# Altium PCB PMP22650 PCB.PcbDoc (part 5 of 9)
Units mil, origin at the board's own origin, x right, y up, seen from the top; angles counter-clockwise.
Board outline 11311 x 5233 mil, 8 copper layers (Layer 1, Layer 2, Layer 3, Layer 4, Layer 5, Layer 6, Layer 7, Layer 8), stack 88.6 mil thick; 633 components, 410 nets, 2503 pads, 1993 vias.
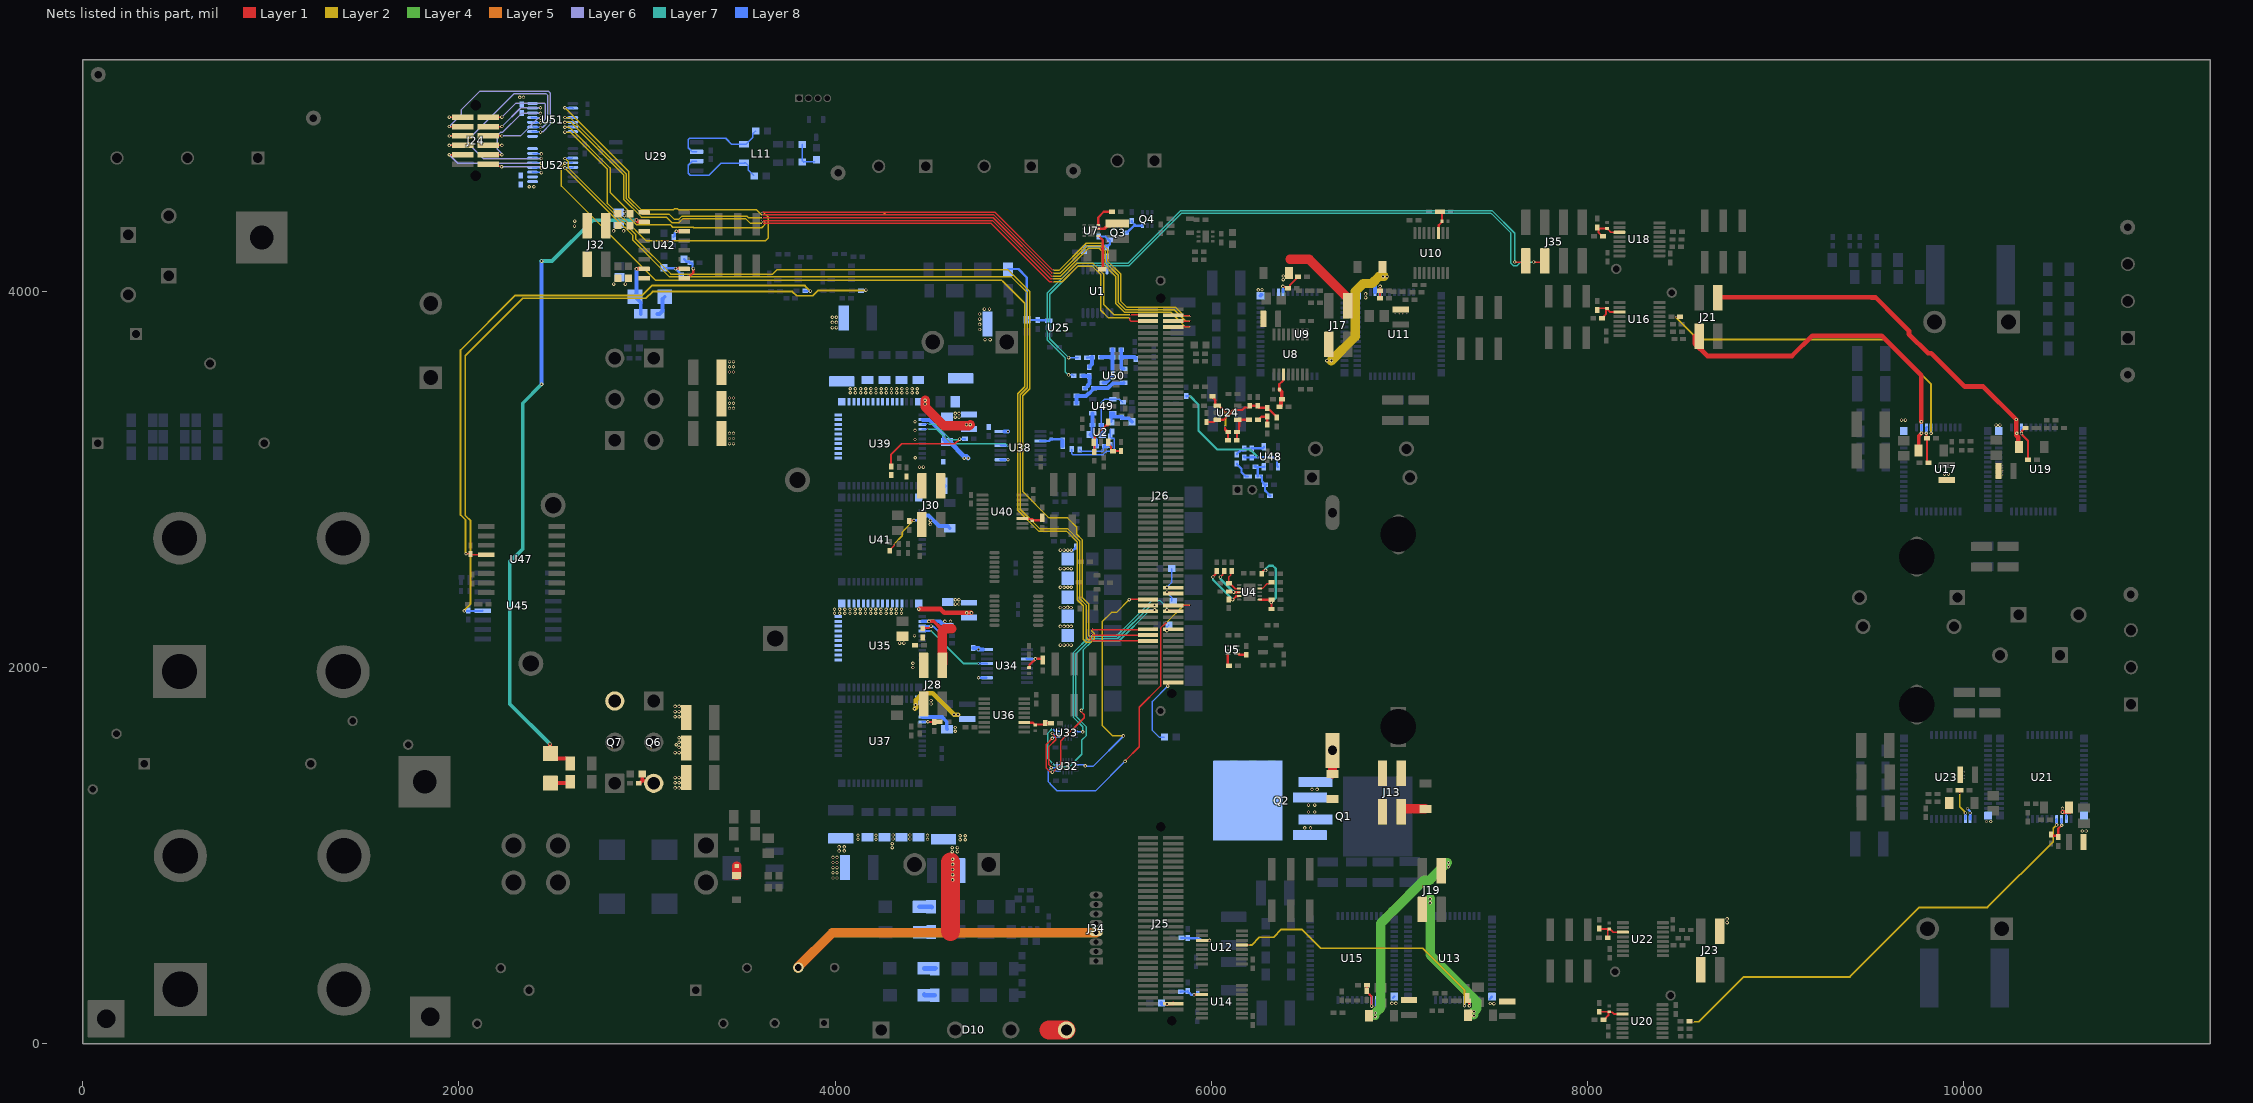
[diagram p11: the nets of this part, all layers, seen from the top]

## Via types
v1: diameter 18, hole 10, Layer 1 to Layer 8, 1759 vias
v2: diameter 8, hole 4, Layer 1 to Layer 2, 160 vias
v3: diameter 18, hole 10, Layer 1 to Layer 8, tented both sides, 34 vias
v4: diameter 8, hole 4, Layer 7 to Layer 8, 28 vias
v5: diameter 19.68, hole 7.87, Layer 1 to Layer 8, 8 vias
v6: diameter 118.11, hole 86.61, Layer 1 to Layer 8, 4 vias

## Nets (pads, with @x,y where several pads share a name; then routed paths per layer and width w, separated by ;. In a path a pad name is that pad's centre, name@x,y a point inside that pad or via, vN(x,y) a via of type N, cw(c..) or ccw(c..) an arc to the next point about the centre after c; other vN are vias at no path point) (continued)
FAULT_L_B: U12.5 U13.46 | length 1469
  Layer 1 w10: U12.5@6162.57,526.05 v2(6201,526)
  Layer 2 w10: v2(6201,526) 6213.5,526 6255.09,567.59 6330.59,567.59 6372,609 6481.43,609 6581.43,509 7123.84,509 7346.44,286.4 7346.44,203.44 v1(7346,203)
  Layer 8 w10: v1(7346,203) 7346.02,232.02 U13.46@7347,233 ; U13.46@7346.03,236.83 U13.46@7348.27,234.6
FAULT_L_C: R211.2 U17.46 | length 1811.7
  Layer 1 w10: v2(8472,3866) R211.2@8482.62,3866
  Layer 2 w10: v2(8472,3866) 8472,3861.41 8588.3,3745.1 9590.06,3745.1 9827,3508.16 v1(9827,3247)
  Layer 8 w10: U17.46@9826,3279 U17.46@9826.94,3278.06 ; U17.46@9826.91,3278.02 U17.46@9826.94,3278.06 ; v1(9827,3247) v1(9827,3247) U17.46@9826.95,3278.05 ; U17.46@9828.04,3279.16 U17.46@9826.94,3278.06
FAULT_L_D: R216.2 U21.46 | length 2463.8
  Layer 1 w10: R216.2@8539,118 v2(8562,118)
  Layer 2 w10: v2(8562,118) 8592,118 8831,357 9394.73,357 9763.73,726 10126,726 10476.23,1076.23 10476.23,1147.23 v1(10494,1165)
  Layer 8 w10: U21.46@10491.18,1192.98 U21.46@10494.05,1195.86 ; U21.46@10493,1194 10494.02,1192.98 v1(10494,1165)
FAULT_L_PFC_1: U34.5 U35.46 | length 417.2
  Layer 7 w10: v4(4510,2195.65) 4683.55,2022.1 v4(4761.97,2022.1)
  Layer 8 w10: U35.46@4463.12,2195.65 v4(4510,2195.65) ; v4(4761.97,2022.1) U34.5@4806.97,2022.1 4807.77,2022.1 U34.5@4808.27,2022.6
FAULT_L_PFC_2: U38.5 U39.46 | length 532.8
  Layer 7 w8: v4(4492.12,3268.14) 4540.59,3268.14 4618.3,3190.43 4907.57,3190.43 v4@4918,3180
  Layer 8 w8: U39.46@4463.27,3268.6 4463.72,3268.14 v4(4492.12,3268.14) ; U38.5@4878.27,3182.6 4879.77,3181.1 v4(4918.97,3181.1)
FET_TEMP_MUX_OUT1: J26.91 U32.6 | length 1299.9
  Layer 1 w8: v1@5569.27,2363.3 5569.37,2363.19 5663.3,2363.19 J26.91@5663.41,2363.09
  Layer 2 w8: v1(5532,1638) 5530.5,1639.5 5473.41,1639.5 5465.5,1647.41 5418.77,1694.14 5418.77,2244.26 5468.9,2294.39 5495.06,2294.39 v1(5563.27,2362.6)
  Layer 8 w8: U32.6@5282.28,1484.35 5323.52,1484.35 v1(5329.27,1478.6) ; v1@5323.27,1477.6 5329.27,1477.6 5373.31,1477.6 5532,1636.29 v1(5532,1638)
FET_TEMP_MUX_OUT2: J26.96 U33.6 | length 1176.9
  Layer 1 w8: v1(5763.27,2307.6) 5765.43,2307.6 5767.09,2305.94 5814.93,2305.94 J26.96@5818.27,2302.6
  Layer 7 w8: v1(5316,1659) 5316,1686.71 5265,1737.71 5265,2078.74 5353.86,2167.6 5494.43,2167.6 5575.93,2249.1 5682.43,2355.6 5729.4,2355.6 5763.27,2321.73 v1(5763.27,2307.6)
  Layer 8 w8: U33.6@5279.42,1662.07 5281.73,1659.76 5315.24,1659.76 v1(5316,1659)
FET_TEMP_MUX_SEL0: J26.93 U32.15 U33.15 | length 1626.4
  Layer 1 w8: J26.93@5633.27,2327.6 J26.93@5698.27,2327.6
  Layer 7 w8: v4(5154.79,1675.68) 5153.66,1675.68 5131.02,1653.04 5131.02,1516.36 v4(5154.79,1492.6) 5173.39,1474 5245.14,1474 5311.27,1540.13 5311.27,1616.1 5335.84,1640.66 5335.84,1685.97 5278.5,1743.3 5278.5,2073.15 5359.45,2154.1 5500.02,2154.1 5677.27,2331.34 5697.01,2331.34 v1(5698.27,2332.6)
  Layer 8 w8: v4(5154.79,1492.6) 5155.73,1492.6 5163.98,1484.35 U32.15@5187.79,1484.35 ; v4(5154.79,1675.68) 5155.98,1675.68 5169.53,1662.13 U33.15@5184.93,1662.07 U33.15@5184.93,1662.07
FET_TEMP_MUX_SEL1: J26.94 U32.14 U33.14 | length 1930.1
  Layer 1 w8: v1@5152.62,1468.6 5136.29,1484.94 5136.29,1581.12 5172.5,1617.34 5172.5,1632.93 v1(5154.79,1650.64) ; v1(5541.27,1502.6) 5541.27,1505.16 5616.5,1580.4 5616.5,1789.68 5730,1903.18 5730,2210.91 5747.59,2228.5 5749.59,2228.5 5760,2238.91 v2(5760,2244) ; J26.94@5783.49,2331.59 J26.94@5797.27,2331.59 ; J26.94@5818.27,2332.6 v2(5888.27,2332.6)
  Layer 2 w8: v2(5760,2244) 5764.67,2244 5853.27,2332.6 v2(5888.27,2332.6)
  Layer 8 w8: v1@5161.27,1646.32 U33.14@5184.93,1646.32 ; U32.14@5187.79,1468.6 5149.6,1468.6 5132,1451 5132,1396.12 5144.74,1383.37 5144.74,1380.42 5177.66,1347.5 5386.17,1347.5 v1(5541.27,1502.6)
  other v1: 5149,1469
FET_TEMP_MUX_SEL2: J26.95 U32.13 U33.13 | length 1519.1
  Layer 1 w8: v1(5154,1625) 5122.79,1593.79 5122.79,1466.21 5142.55,1446.45 5155.86,1446.45 5157.33,1444.98 5173.29,1460.94 5173.29,1462.35 5200,1489.07 5200,1544.7 5199.77,1544.94 5199.77,1610.84 5323.87,1734.94 5323.87,1750.26 5309.17,1764.96 v1(5309.17,1773.25) ; J26.95@5663.41,2300.09 5669.25,2305.94 5694.44,2305.94 5696.1,2307.6 v1(5698.27,2307.6)
  Layer 7 w8: v1(5309.17,1773.25) 5318.27,1782.34 5318.27,2093.83 5365.04,2140.6 5507.18,2140.6 5674.18,2307.6 v1(5698.27,2307.6)
  Layer 8 w8: v1(5154,1625) 5159.57,1630.57 U33.13@5184.93,1630.57 ; v1(5154.79,1444.98) 5156.95,1444.98 5165.05,1453.08 5179.82,1453.08 5180.04,1452.85 U32.13@5187.79,1452.85
FSI_TX_CLK: J26.105 U52.3 | length 5218.2
  Layer 1 w8: v2(5348.27,2162.6) 5368.27,2142.6 J26.105@5643.27,2142.6
  Layer 2 w8: v1(2563.27,4707.6) 2564.43,4707.6 2581.77,4690.26 2581.77,4656.98 2866.75,4372 2871.79,4372 2938.5,4305.29 2938.5,4281.19 3126.69,4093 3667.79,4093 3690.89,4116.1 4125.93,4116.1 4127.03,4115 4920,4115 5034.5,4000.5 5034.5,3483.22 4997.5,3446.22 4997.5,2936.5 5137.5,2796.5 5235.53,2796.5 5284.5,2747.53 5284.5,2709.78 5314.36,2679.91 5314.36,2372.55 5348.27,2338.64 v2(5348.27,2162.6)
  Layer 8 w8: v1(2563.27,4707.6) 2564.52,4708.85 2599.52,4708.85 U52.3@2603.27,4712.6
FSI_TX_D0: J26.101 U52.4 | length 5332.1
  Layer 1 w8: v2(5363.27,2207.6) 5368.27,2202.6 5628.27,2202.6 J26.101@5633.27,2207.6
  Layer 2 w8: v1(2563.27,4682.6) 2562.1,4682.6 2544.77,4665.26 2544.77,4561.24 3046.51,4059.5 4886.31,4059.5 4891,4054.81 5007.5,3938.31 5007.5,3494.41 4970.5,3457.41 4970.5,2837.41 5081.41,2726.5 5229.59,2726.5 5287.36,2668.73 5287.36,2361.36 5319.06,2329.67 5319.06,2151.94 5335,2136 5336.68,2136 5337.08,2135.6 5360.6,2135.6 5375,2150 5375,2151.15 5376.77,2152.91 5376.77,2183.19 5363.27,2196.69 v2(5363.27,2207.6)
  Layer 8 w8: v1(2563.27,4682.6) 2564.52,4683.85 2599.52,4683.85 U52.4@2603.27,4687.6
FSI_TX_D1: J26.103 U52.5 | length 5215.1
  Layer 1 w8: v2(5363.27,2177.6) 5368.27,2172.6 5633.27,2172.6 J26.103@5638.27,2177.6
  Layer 2 w8: v1(2563.27,4657.6) 2563.27,4656.39 2878.05,4341.6 2883.1,4341.6 2893.94,4330.77 2893.94,4330.06 2925,4299 2925,4272.69 3119.69,4078 4937.91,4078 5021,3994.91 5021,3488.82 4984,3451.82 4984,2843 5087,2740 5235.18,2740 5300.86,2674.32 5300.86,2366.96 5334.27,2333.55 5334.27,2157.51 5342.68,2149.1 5353.86,2149.1 5363.27,2158.51 v2(5363.27,2177.6)
  Layer 8 w8: v1(2563.27,4657.6) 2564.52,4658.85 2604.52,4658.85 U52.5@2608.27,4662.6
IAC_PH1_SENSOR: C211.1 R146.1 U47.12 | length 3250
  Layer 1 w10: v1@2036,2605 v1(2037,2606) 2059.24,2606 C211.1@2061.27,2603.98 ; C211.1@2059,2604 2062,2601 U47.12@2144.99,2601
  Layer 2 w10: v1@2035,2613.66 2035,2785.72 2008,2812.72 2008,3689.33 2298.67,3980 2974,3980 3025.5,4031.5 3839.37,4031.5 v1(3868.27,4002.6)
  Layer 8 w10: R146.1@3833.27,4002.6 3833.75,4003.08 3867.78,4003.08 v1(3868.27,4002.6)
IAC_PH2_SENSOR: C204.1 R131.1 U45.12 | length 3806.6
  Layer 2 w10: v1@2025,2303 2026.5,2303 2029.8,2306.29 2029.8,2307.8 2062,2340 2062,2780.64 2033,2809.64 2033,3659.33 2338.17,3964.5 2993.87,3964.5 3029.72,4000.35 3772.25,4000.35 3794.6,3978 3880,3978 3907.64,4005.64 4157.07,4005.64 4157.88,4006.45 v1@4163.42,4006.45
  Layer 8 w10: v1(2028.27,2302.6) 2125.26,2302.6 U45.12@2126.26,2303.6 ; R131.1@4133.27,4007.6 4134.42,4006.45 4162.12,4006.45 v1(4163.27,4007.6)
IN_H_A: C57.2 R34.2 U11.45 | length 103
  Layer 1 w10: v1@6897,4029 6897.27,4028.73 v1(6897.27,4028) 6897.27,4004.11 C57.2@6897.38,4004 6897.38,3966.62 R34.2@6901,3963
  Layer 8 w10: U11.45@6897,3993 6896.72,3993.28 6896.72,4027.45 v1(6897.27,4028)
IN_H_B: C79.2 R44.2 U15.45 | length 155.9
  Layer 1 w12: R44.2@6826.62,313 6826.81,312.81 6826.81,281.19 C79.2@6827,281 ; C79.2@6827,280.62 6827,276.68 6841.85,261.83 6842.37,261.83 6852,252.2 v1(6852,201)
  Layer 8 w12: U15.45@6851,234 6851.81,233.19 6851.81,201.19 v1(6852,201)
IN_H_C: C101.2 R54.2 U19.45 | length 239.7
  Layer 1 w12: v1(10307,3246) 10307,3244.38 10311.5,3239.88 10311.5,3237.51 10342.38,3206.63 10342.38,3106.38 R54.2@10342,3106 ; v1@10308,3247 10308.15,3247.15 10308.15,3258.71 10324.44,3275 C101.2@10328.38,3275 10330.07,3275 C101.2@10335.88,3269.19 ; C101.2@10325.44,3274 C101.2@10330,3274
  Layer 8 w12: U19.45@10306.31,3278.02 10306.66,3277.68 10306.66,3248.34 v1@10308,3247
IN_H_D: C123.2 R64.2 U23.45 | length 165.5
  Layer 1 w10: R64.2@9978,1347 9979,1346 v2(9979,1331)
  Layer 2 w10: v2(9979,1331) 9979,1260.58 10003.5,1236.08 10003.5,1235.66 10008,1231.16 v3@10008,1226
  Layer 8 w12: U23.45@10009,1196 10008.9,1196.1 10008.9,1227.9 v3(10009,1228)
IN_H_PFC_1: C165.2 R105.2 U37.45 | length 95.3
  Layer 1 w10: v1@4492.9,1712.6 v1(4493.12,1712.82) 4493.34,1712.6 4525.35,1712.6 4526.47,1711.47 C165.2@4527.09,1710.85 ; C165.2@4525,1710 4527,1712 R105.2@4554.38,1712
  Layer 8 w10: U37.45@4463.27,1712.6 4463.49,1712.82 v1(4493.12,1712.82)
IN_H_PFC_2: C187.2 R115.2 U41.45 | length 296.5
  Layer 1 w8: R115.2@4293,2622 4293,2628.31 4313,2648.31 v2(4313,2658) ; C187.2@4387.37,2771.37 C187.2@4390,2774 ; C187.2@4389,2782.62 4390.38,2784 4418,2784 v1@4421,2781 ; v1(4419,2784) v1@4420,2785
  Layer 2 w8: v2(4313,2658) 4356.5,2701.5 4356.5,2722.26 4417,2782.76 v1@4417,2783
  Layer 8 w12: v1@4418,2784 v1(4419,2784) 4462.96,2784 U41.45@4463.12,2784.16
IN_L_A: C42.2 R29.2 U9.45 | length 153.4
  Layer 1 w10: v1@6379,4029 6382.16,4029 6385.76,4025.41 6399.83,4025.41 C42.2@6406.65,4018.6 ; C42.2@6408,4020 6411.98,4020 6417.39,4025.41 6417.39,4034.02 6450.63,4067.25 6450.63,4071.19 6457.44,4078 R29.2@6461.38,4078
  Layer 8 w10: U9.45@6380,3996 6380.76,3996.76 6380.76,4027.24 v1(6380,4028) ; U9.45@6381.52,3996.71 U9.45@6384.39,3999.59
IN_L_B: C64.2 R39.2 U13.45 | length 96.9
  Layer 1 w12: R39.2@7361,258.38 7362.31,257.07 7362.31,231.69 C64.2@7365,229 ; C64.2@7363,233 7370.85,225.15 7370.85,204.15 v1(7372,203)
  Layer 8 w12: v1(7372,203) 7371.81,203.19 7371.81,234.81 U13.45@7372,235
IN_L_C: C86.2 R49.2 U17.45 | length 198.5
  Layer 1 w12: v1(9801,3247) 9802.15,3245.85 9802.15,3224.85 C86.2@9805,3222 ; C86.2@9804.38,3221 9804.38,3094.81 9812.19,3087 R49.2@9814,3087
  Layer 8 w12: v1(9801,3247) 9801.16,3247.16 9801.16,3277.16 U17.45@9803,3279
IN_L_D: C108.2 R59.2 U21.45 | length 139.7
  Layer 1 w12: R59.2@10464,1112.62 10464,1112.43 10469.81,1106.62 10498.38,1106.62 C108.2@10499.13,1105.87 ; C108.2@10503,1100.62 10503,1145 v1(10521,1163)
  Layer 8 w12: v1@10519.64,1164 U21.45@10519.64,1195.86
IN_L_PFC_1: C150.2 R100.2 U35.45 | length 181.6
  Layer 1 w10: C150.2@4466.27,2209.22 4469.05,2212 4499.13,2212 4508.37,2221.24 v1(4510,2221.24)
  Layer 8 w10: U35.45@4463.12,2221.24 v1(4510,2221.24) 4511.14,2220.1 4520.31,2220.1 4570.71,2169.7 R100.2@4574.65,2169.7
IN_L_PFC_2: C172.2 R110.2 U39.45 | length 726.4
  Layer 1 w10: C172.2@4297.27,3076.27 4297.27,3135.53 4352.74,3191 4637,3191 v1(4662,3216)
  Layer 7 w8: v4(4492.12,3293.73) 4534.09,3293.73 4616.09,3211.73 v1@4666.27,3211.73
  Layer 8 w8: U39.45@4463.12,3293.73 4463.25,3293.6 v4@4493.27,3293.6
  Layer 8 w10: v1(4662,3216) 4662.61,3216.61 4688.26,3216.61 R110.2@4690.27,3214.6 ; R110.2@4689.65,3216.62 R110.2@4690.65,3215.62
INJ: C235.1 J34.4 | length 1665.8
  Layer 5 w50: C235.1@3800,406 3985.44,591.44 J34.4@5387.63,591.44
  Layer 2 w50: C235.1@3804.26,406.24 C235.1@3805.24,407.22
IPRI_SENSE: C146.1 C148.2 C150.1 C151.2 C152.2 C153.2 C154.2 C155.1 C156.1 C157.2 C158.2 C159.1 C160.1 C168.1 C170.2 C172.1 C173.2 C174.2 C175.2 C176.2 C177.1 C178.1 C179.2 C180.2 C181.1 C182.1 C190.1 C191.1 C192.1 C196.2 C226.1 C227.1 C228.1 C229.1 C230.1 C231.1 D10.4 J28.4 J30.4 J32.4 L12.1 L14.1 Q6.3 Q7.3 R82.1 R97.1 R107.1 R118.1 R159.1 R164.1 R166.1 R171.1 R172.1 U34.2 U34.8 U35.17 U35.18 U35.19 U35.20 U35.21 U35.22 U35.23 U35.24 U35.25 U35.26 U35.27 U35.28 U35.29 U35.30 U35.31 U35.32 U35.33 U35.34 U35.35 U35.36 U35.37 U35.38 U35.39 U38.2 U38.8 U39.17 U39.18 U39.19 U39.20 U39.21 U39.22 U39.23 U39.24 U39.25 U39.26 U39.27 U39.28 U39.29 U39.30 U39.31 U39.32 U39.33 U39.34 U39.35 U39.36 U39.37 U39.38 U39.39 U42.9 | length 775.6
  Layer 1 w20: C196.2@2955.89,1385.6 2959.83,1385.6 2973.76,1399.54 ; R118.1@2973.76,1435.6 2973.76,1400.1 2974.29,1399.58 3021.33,1399.58 Q6.3@3035.21,1385.7
  Layer 1 w100: 4613.27,598.6 4613.27,872.6 4613.27,967.6 ; 5136.87,75 D10.4@5227,75
  Layer 5 w12: 4262.77,4418.1 4263.27,4417.6
  Layer 8 w12: v1(4761.97,1947.1) 4802.77,1947.1 U34.2@4803.27,1947.6 ; U38.2@4878.27,3107.6 4879.77,3106.1 v1(4918.97,3106.1) ; v1@5253.27,2624.6 5264.83,2624.6 5280.27,2640.04 R82.1@5280.27,2643.98
  Layer 8 w20: C148.2@4735.27,2104.75 v1@4761.97,2104.75 ; v1(4761.97,2097.1) 4762.68,2097.8 U34.8@4785.47,2097.8 ; U38.8@4900.46,3256.1 v1(4918.97,3256.1)
  other v1: 4624.54,872.6 3988.27,882.6 4009.54,882.6 4624.54,900.01 3988.27,910.01 4009.54,910.01 4624.54,927.41 3988.27,937.41 4009.54,937.41 4624.54,954.82 3988.27,964.82 4009.54,964.82 4624.54,982.23 3988.27,992.23 4009.54,992.23 4622.17,1022.72 4649.58,1022.72 4020.94,1026.72 4048.35,1026.72 4303.39,1043.72 4622.17,1044 4649.58,1044 4020.94,1048 4048.35,1048 4303.39,1065 4664.03,1085.72 4691.43,1085.72 4490.84,1087.72 4121.54,1088.72 4216.76,1088.72 4307.98,1089.72 4397.21,1089.72 4664.03,1107 4691.43,1107 4490.84,1109 4121.54,1110 4216.76,1110 4307.98,1111 4397.21,1111 3149.27,1361.59 3170.54,1361.59 3149.27,1389 3170.54,1389 3149.27,1416.41 3170.54,1416.41 3149.27,1549.26 3170.54,1549.26 3170.54,1576.66 3155,1591 3170.54,1604.07 3170,1628 3149.27,1739.78 3170.54,1739.78 3149.27,1767.19 3170.54,1767.19 3149.27,1794.6 3170.54,1794.6 4413.27,2001.49 4413.27,2024.28 5197.09,2120.85 5217.09,2120.85 5235.64,2121.16 5254.18,2120.85 4343,2131.24 4365.27,2131.24 4422,2171 5197.09,2220.21 5217.09,2220.21 5254.18,2220.21 5235.64,2220.52 3996.5,2289.69 4023.91,2289.69 4051.32,2289.69 4078.73,2289.69 4106.14,2289.69 4133.54,2289.69 4160.95,2289.69 4188.36,2289.69 4215.77,2289.69 4243.18,2289.69 4270.59,2289.69 4297.99,2289.69 4325.4,2289.69 4352.81,2289.69 3996.5,2310.97 4023.91,2310.97 4051.32,2310.97 4078.73,2310.97 4106.14,2310.97 4133.54,2310.97 4160.95,2310.97 4188.36,2310.97 4215.77,2310.97 4243.18,2310.97 4270.59,2310.97 4297.99,2310.97 4325.4,2310.97 4352.81,2310.97 5197.09,2320.56 5217.09,2320.56 5235.64,2320.87 5254.18,2320.56 4639.27,2338.63 4658,2339 4639.27,2361.43 4658,2362 5197.09,2428.04 5217.09,2428.04 5236.82,2428.35 5255.36,2428.04 5197.09,2527.39 5217.09,2527.39 5255.36,2527.39 5236.82,2527.7 5197.09,2625.3 5217.09,2625.3 5255.36,2625.3 5236.82,2625.61 4448.09,3067.17 4468.97,3067.17 4426,3117 3438.27,3191.59 3459.54,3191.59 4424.17,3214 3438.27,3219 3459.54,3219 3438.27,3246.41 3459.54,3246.41 4424.17,3262 4424.17,3308.36 4638.27,3332.6 4658.27,3332.6 4638.27,3352.6 4658.27,3352.6 3438.27,3379.26 3459.54,3379.26 3438.27,3406.66 3459.54,3406.66 3438.27,3434.07 3459.54,3434.07 4080.22,3462.52 4107.62,3462.52 4135.03,3462.52 4162.44,3462.52 4189.85,3462.52 4217.26,3462.52 4244.66,3462.52 4272.07,3462.52 4299.48,3462.52 4326.89,3462.52 4354.3,3462.52 4381.71,3462.52 4409.11,3462.52 4436.52,3462.52 4080.22,3483.8 4107.62,3483.8 4135.03,3483.8 4162.44,3483.8 4189.85,3483.8 4217.26,3483.8 4244.66,3483.8 4272.07,3483.8 4299.48,3483.8 4326.89,3483.8 4354.3,3483.8 4381.71,3483.8 4409.11,3483.8 4436.52,3483.8 3438.27,3572.78 3459.54,3572.78 3438.27,3600.19 3459.54,3600.19 3438.27,3627.6 3459.54,3627.6 4796.4,3744.77 4823.8,3744.77 4768.04,3798.6 3984.97,3808.78 4006.24,3808.78 4768.04,3826.01 3984.97,3836.19 4006.24,3836.19 4768.04,3853.42 3984.97,3863.6 4006.24,3863.6 4768.04,3880.83 4793.17,3906.77 4820.58,3906.77 2614.27,4348.08 2615.19,4374.6 2880,4404 2880,4425
ISNS_OUTN: J35.5 R199.1 | length 3441.9
  Layer 1 w8: v1(7713.02,4157.18) 7753.02,4157.18 7757.85,4157.18 J35.5@7758.27,4157.6
  Layer 7 w8: v1(5240.94,3649) 5141,3748.94 5141,3986.49 5293.01,4138.5 5563.59,4138.5 5842.59,4417.5 7484.5,4417.5 7486.86,4415.14 7488.96,4415.14 7593,4311.1 7593,4151 7605.32,4138.68 7626.68,4138.68 7645.18,4157.18 7710.18,4157.18 v1@7712,4159
  Layer 8 w8: v1(5240.94,3649) R199.1@5291.29,3649
ISNS_OUTP: J35.7 R195.1 | length 3423.7
  Layer 1 w8: v1(7613.02,4157.18) 7653.02,4157.18 7657.85,4157.18 J35.7@7658.27,4157.6
  Layer 2 w8: v1@5239,3557 v1@5240,3556
  Layer 7 w8: v1@5236,3560 5222.44,3573.56 5222.44,3648.41 5127.5,3743.34 5127.5,3992.5 5287,4152 5558,4152 5837,4431 7492.19,4431 7613.02,4310.17 v1(7613.02,4157.18)
  Layer 8 w8: v1(5241,3557) 5263.64,3557 R195.1@5268.32,3552.31
ISO_3.3V: C252.2 C254.2 J24.8 U51.1 U52.10 U52.16 | length 72.5
  Layer 1 w8: J24.8@2155.79,4777.6 v1(2228.27,4777.6)
ISO_12V_H_A: C59.1 J17.3 U11.44 | length 723.7
  Layer 2 w25: 6893,4079.6 v1(6913,4079.6)
  Layer 2 w50: v1(6638,3633) 6765,3760 6765,4000.47 6807.71,4043.18 6854.18,4043.18 6893,4082 v1@6918,4082
  Layer 8 w20: U11.44@6870.58,3996.71 6870.58,4050.58 6901,4081
  other v1: 6614,3633 6934,4079.6
ISO_12V_H_B: C81.1 J19.3 U15.44 | length 1061.3
  Layer 1 w25: J19.3@7211.36,949.36 J19.3@7222,960
  Layer 4 w50: v1@6870,153 6870,163.33 v1(6871.27,164.6) 6871.46,164.6 6901.5,194.64 6901.5,642.5 6967,708 ; 6961.5,702.12 7130.55,871.17 7160.89,871.17 v1@7253.89,964.17
  Layer 8 w12: v1(6871.27,164.6) v1@6871.27,166.22 ; 6877,185 6877.21,185.21 U15.44@6877.21,233.3
  other v1: 6870.43,145.48 7260.89,942 7260.89,963.17
ISO_12V_H_C: C103.1 J21.3 U19.44 | length 2083.8
  Layer 1 w25: J21.3@8693,3972 8694.43,3970.56 9506.6,3970.56 9508.13,3969.04 9530.96,3969.04 9649.47,3850.53 9708.72,3791.28 9708.72,3774.28 9810.23,3672.77 9827.23,3672.77 9886.49,3613.51 10005,3495 10104,3495 v1(10279,3320) v1@10279,3247 ; 10279,3235.82 10289.85,3224.96 10289.85,3177.22 C103.1@10294.07,3173
  Layer 8 w12: v1(10279,3320) 10279.86,3319.14 10279.86,3277.14 U19.44@10281,3276 ; U19.44@10280.72,3278.02 10281.36,3277.39 v1@10281.36,3247.36
  other v1: 10282,3247
ISO_12V_H_D: C125.1 J23.3 U23.44 | length 64.2
  Layer 8 w12: v3(10020,1252) 10020,1250.38 10032.85,1237.52 10032.85,1228.15 v3@10034,1227 ; v3(10034,1228) 10034.19,1227.81 10034.19,1195.81 U23.44@10035,1195
  other v1: 8742.27,644.83 8742.27,664.85
ISO_12V_H_PFC_1: C167.1 J28.3 U37.44 | length 181
  Layer 8 w20: U37.44@4463.12,1738.41 4567.33,1738.41 4592.92,1712.82 4592.92,1675.52 C167.1@4595.27,1673.17
  other v1: 4638.27,1662.6 4638.27,1682.6 4510,1807.6 4510,1826.23
ISO_12V_H_PFC_2: C189.1 J30.3 U41.44 | length 174.3
  Layer 8 w20: U41.44@4463.12,2809.75 4496.12,2809.75 4552.54,2753.32 4597.61,2753.32 C189.1@4609.27,2741.67
  other v1: 4506.27,2762.6 4506.27,2782.6
ISO_12V_H_RECT: C199.2 C200.2 C201.2 J32.3 U42.16
  other v1: 2822.5,4040.1 2884.5,4040.1
ISO_12V_L_A: C44.1 J17.2 U9.44 | length 434.1
  Layer 1 w50: 6418,4171 6520.78,4171 6725.01,3966.78 J17.2@6725.01,3924.26
  other v1: 6382,4064 6382,4083
ISO_12V_L_B: C66.1 J19.2 U13.44 | length 884.1
  Layer 1 w12: C66.1@7364,170 7366,172 v1(7396,172) ; C66.1@7366,151 v1(7396,151)
  Layer 1 w25: J19.2@7122,715.31 J19.2@7134.5,702.81
  Layer 4 w50: v1(7162.89,771.17) 7162.89,474.25 7411.5,225.64 7411.5,186.64 7396,171.14 v1@7396,156
  Layer 8 w12: v1@7394,171 7396.61,173.61 7396.61,232.69 U13.44@7397.21,233.3 7399.09,231.42 U13.44@7399.09,218.63
  other v1: 7162.97,749.87
ISO_12V_L_C: C88.1 J21.2 U17.44 | length 1812.5
  Layer 1 w20: C88.1@9761,3154 9761,3233 v1(9775,3247)
  Layer 1 w25: J21.2@8571.15,3765.45 8571.15,3722.93 8635.98,3658.1 9087.1,3658.1 9195,3766 9564,3766 9774,3556 v1@9774,3308.26
  Layer 8 w12: v1(9774.83,3308.26) 9775.28,3307.82 9775.28,3277.72 U17.44@9775.72,3277.28 ; v1@9775.72,3247 U17.44@9775.72,3277.28 ; U17.44@9776,3277 U17.44@9775.72,3277.28
ISO_12V_L_D: C110.1 J23.2 U21.44 | length 89.1
  Layer 1 w20: v3(10525.27,1232.86) 10552.5,1232.86 10552.7,1233.06 C110.1@10562.54,1233.06
  Layer 8 w10: v3(10525.27,1232.86) 10536.23,1232.86 10545.23,1223.86 U21.44@10545.23,1195.86
  other v3: 10525.05,1252.37
ISO_12V_L_PFC_1: C152.1 J28.2 U35.44 | length 481.9
  Layer 1 w20: v1(4498.12,2246.83) 4498.77,2247.49 4524.17,2247.49 4564.86,2206.8 4583.4,2206.8
  Layer 1 w50: J28.2@4570.87,2021.06 4570.87,2077.06 4570,2077.92 4570,2195.33 4581.47,2206.8 4583.4,2206.8 ; 4581.27,2206.6 4619.88,2206.6
  Layer 8 w20: U35.44@4463.12,2246.83 4557.26,2246.83 4588.43,2215.67 C152.1@4598.27,2215.67
  other v1: 4583.4,2246.8 4613.27,2246.8
ISO_12V_L_PFC_2: C174.1 J30.2 U39.44 | length 335.1
  Layer 8 w20: U39.44@4463.12,3319.32 4465.24,3317.2 4499.67,3317.2 4576.77,3240.09 4576.77,3212.87 C174.1@4588.43,3201.21
  Layer 8 w25: C174.1@4598.27,3201.21 4608.11,3201.21 4686.48,3122.85 4699.11,3122.85 v1(4707.36,3114.6)
  other v1: 4686.48,3114.6
ISO_12V_L_RECT: C190.2 C191.2 C192.2 J32.2 U42.11
  other v1: 2822.44,4323.1 2875.44,4323.1
ISO_ETAS_GND: C252.1 C254.1 J24.1 U51.8 U52.9 U52.11 U52.15 | length 170.6
  Layer 1 w8: v1(1948.27,4927.6) J24.1@2020.75,4927.6
  Layer 8 w8: U52.11@2388.27,4637.6 2392.02,4633.85 2437.02,4633.85 v1(2438.27,4632.6) ; U52.15@2393.27,4732.6 2394.52,4733.85 2437.02,4733.85 v1(2438.27,4732.6)
  other v1: 2373.27,4557.6 2398.27,4557.6 2323.27,5032.6 2343.27,5032.6
ISO_FSI_TX_CLK: J24.7 U52.14 | length 638.5
  Layer 1 w8: v1(1948.27,4777.6) J24.7@2020.75,4777.6
  Layer 6 w8: v1(1948.27,4777.6) 2059.22,4777.6 2129.22,4707.6 v1(2438.27,4707.6)
  Layer 8 w8: U52.14@2393.27,4712.6 2397.02,4708.85 2437.02,4708.85 v1(2438.27,4707.6)
ISO_FSI_TX_D0: J24.9 U52.13 | length 627.2
  Layer 1 w8: v1@1953.27,4727.6 J24.9@2020.75,4727.6
  Layer 6 w8: v1(1948.27,4727.6) 1993.27,4682.6 v1(2438.27,4682.6)
  Layer 8 w8: U52.13@2388.27,4682.6 2389.52,4683.85 2437.02,4683.85 v1(2438.27,4682.6)
ISO_FSI_TX_D1: J24.12 U52.12 | length 342.9
  Layer 1 w8: J24.12@2155.79,4677.6 2166.35,4667.03 2221.26,4667.03 2223.64,4664.65 v1@2227.35,4664.65
  Layer 6 w8: v1(2227,4664) 2431.87,4664 v1(2438.27,4657.6)
  Layer 8 w8: U52.12@2388.27,4662.6 2392.02,4658.85 2437.02,4658.85 v1(2438.27,4657.6)
ISO_JTAG-TCK-ETAS-Header-2: J24.2 U51.4 | length 500.3
  Layer 1 w8: J24.2@2148.27,4927.6 J24.2@2155.79,4927.6 v1(2228.27,4927.6)
  Layer 6 w8: v1(2228.27,4927.6) 2302.67,5002 2454.77,5002 2459.45,4997.31 2459.45,4917.45 2441.51,4899.51 2435.18,4899.51 v1(2433.27,4897.6)
  Layer 8 w8: U51.4@2393.27,4902.6 2397.02,4898.85 2432.02,4898.85 v1(2433.27,4897.6)
ISO_JTAG-TDI-ETAS-Header-6: J24.6 U51.5 | length 368.9
  Layer 1 w8: J24.6@2155.79,4827.6 v1(2228.27,4827.6)
  Layer 6 w8: v1(2228.27,4827.6) 2326.6,4827.6 2420.58,4921.58 2432.25,4921.58 v1(2433.27,4922.6)
  Layer 8 w8: U51.5@2383.27,4927.6 2387.02,4923.85 2432.02,4923.85 v1(2433.27,4922.6)
ISO_JTAG-TDO-ETAS-Header-4: J24.4 U51.7 | length 364.9
  Layer 1 w8: J24.4@2155.79,4877.6 v1(2228.27,4877.6)
  Layer 6 w8: v1(2228.27,4877.6) 2328.27,4977.6 v1(2433.27,4977.6)
  Layer 8 w8: U51.7@2388.27,4977.6 2389.52,4976.35 2432.02,4976.35 v1(2433.27,4977.6)
ISO_JTAG-TMS-ETAS-Header-5: J24.5 U51.3 | length 924.8
  Layer 1 w8: v1(1948.27,4827.6) J24.5@2020.75,4827.6
  Layer 6 w8: v1@1953.27,4827.6 2068.27,4827.6 2293.27,5052.6 2463.27,5052.6 2472.95,5042.91 2472.95,4900.95 2445.78,4873.78 2434.45,4873.78 v1(2433.27,4872.6)
  Layer 8 w8: U51.3@2393.27,4877.6 2397.02,4873.85 2432.02,4873.85 v1(2433.27,4872.6)
ISO_JTAG-TRSTn-ETAS-Header-3: J24.3 U51.2 | length 990.5
  Layer 1 w8: v1(1948.27,4877.6) J24.3@2020.75,4877.6
  Layer 6 w8: v1(1948.27,4877.6) 2011.28,4940.61 2011.28,4966.17 2111.2,5066.1 2474.77,5066.1 2486.45,5054.41 2486.45,4890.45 2445.28,4849.28 2434.95,4849.28 v1(2433.27,4847.6)
  Layer 8 w8: U51.2@2388.27,4852.6 2392.02,4848.85 2432.02,4848.85 v1(2433.27,4847.6)
ISO_XRSn: J24.10 U51.6 | length 504.3
  Layer 1 w8: J24.10@2155.79,4727.6 v1(2228.27,4727.6)
  Layer 6 w8: v1@2228.27,4732.6 2203.27,4757.6 2203.27,4828.76 2220.6,4846.1 2230.1,4846.1 2331.6,4947.6 v1(2433.27,4947.6)
  Layer 8 w8: U51.6@2388.27,4947.6 2389.52,4948.85 2432.02,4948.85 v1(2433.27,4947.6)
JTAG-TCK-ETAS-Header-2: J26.5 U51.13 | length 3833.2
  Layer 1 w8: v2(3613.27,4362.6) 4829.4,4362.6 5139.4,4052.6 v2(5158.27,4052.6) ; v2(5567,3862) 5567,3848.87 5573.27,3842.6 J26.5@5638.27,3842.6
  Layer 2 w8: v1@2566.27,4899.6 2596.47,4899.6 2876,4620.07 2876,4489.82 2969.82,4396 3102,4396 3132,4366 3169,4366 3191,4388 3524,4388 3549.4,4362.6 v2(3613.27,4362.6) ; v2(5158.27,4052.6) 5206.97,4052.6 5290.47,4136.1 5365.9,4136.1 5411.77,4090.23 5411.77,3901.23 5451,3862 v2(5567,3862)
  Layer 8 w8: v1(2563.27,4899.6) 2563.52,4899.85 2600.52,4899.85 U51.13@2603.27,4902.6
JTAG-TDI-ETAS-Header-6: J26.8 U51.12 | length 4233
  Layer 1 w8: v2(3613.27,4392.6) 4840.08,4392.6 5150.08,4082.6 v2(5158.27,4082.6) ; J26.8@5818.27,3812.6 v2(5888.27,3812.6)
  Layer 2 w8: v1@2566.27,4925.6 2589.56,4925.6 2889.5,4625.66 2889.5,4495.41 2974.91,4410 3118.84,4410 3127.34,4401.5 3145.34,4383.5 3167.41,4383.5 3185.41,4401.5 3529.59,4401.5 3538.49,4392.6 v2(3613.27,4392.6) ; v2(5158.27,4082.6) 5198.78,4082.6 5346.28,4230.1 5403.9,4230.1 5419,4215 5419,4154 5492,4081 5492,3936.59 5538.09,3890.5 5784.46,3890.5 5862.36,3812.6 v2(5888.27,3812.6)
  Layer 8 w8: v1(2563.27,4925.6) 2563.52,4925.35 2605.52,4925.35 U51.12@2608.27,4922.6
JTAG-TDO-ETAS-Header-4: J26.6 U51.10 | length 4242.5
  Layer 1 w8: v2(3613.27,4407.6) 4844.18,4407.6 5144.77,4107.01 5154.18,4097.6 v2(5158.27,4097.6) ; J26.6@5813.27,3842.6 v2(5888.27,3842.6)
  Layer 2 w8: v1(2563.27,4977.6) 2563.43,4977.6 2581.77,4959.26 2581.77,4959.1 2903,4637.87 2903,4501 2968,4436 3140.84,4436 3145.34,4440.5 3160.66,4440.5 3165.16,4436 3580.77,4436 3609.18,4407.6 v2(3613.27,4407.6) ; v2(5158.27,4097.6) 5194.69,4097.6 5340.69,4243.6 5409.49,4243.6 5434.77,4218.32 5434.77,4157.32 5505.5,4086.59 5505.5,3942.18 5543.68,3904 5802.87,3904 5864.27,3842.6 v2(5888.27,3842.6)
  Layer 8 w8: v1(2563.27,4977.6) 2564.52,4976.35 2604.52,4976.35 U51.10@2608.27,4972.6
JTAG-TMS-ETAS-Header-5: J26.3 U51.14 | length 3849.1
  Layer 1 w8: v2(3613.27,4377.6) 4835.99,4377.6 5145.99,4067.6 v2(5158.27,4067.6) ; v2(5570,3877) 5628.87,3877 J26.3@5633.27,3872.6
  Layer 2 w8: v1(2563.27,4873.6) 2587.27,4873.6 2803,4657.87 2803,4528.16 2898.5,4432.66 2898.5,4400.34 2942.74,4356.1 3122.81,4356.1 3136.41,4342.5 3245.66,4342.5 3248.59,4339.57 3610.15,4339.57 3626.77,4356.19 3626.77,4368.19 3617.36,4377.6 v2(3613.27,4377.6) ; v2(5158.27,4067.6) 5202.87,4067.6 5284.87,4149.6 5371.49,4149.6 5427,4094.09 5427,3932.84 5482.84,3877 v2(5570,3877)
  Layer 8 w8: v1(2563.27,4873.6) 2564.02,4874.35 2600.02,4874.35 U51.14@2603.27,4877.6
JTAG-TRSTn-ETAS-Header-3: J26.4 U51.15 | length 4429.5
  Layer 1 w8: v2(3613.27,4422.6) 4848.27,4422.6 v2(5158.27,4112.6) ; J26.4@5828.27,3872.6 v2(5888.27,3872.6)
  Layer 2 w8: v1(2563.27,4847.6) 2592.4,4847.6 2789.5,4650.5 2789.5,4468.34 2872.34,4385.5 2879.5,4385.5 2995,4270 3629,4270 3644,4285 3644,4395.96 3618.86,4421.1 3614.77,4421.1 v2(3613.27,4422.6) ; v2(5158.27,4112.6) 5190.6,4112.6 5335.1,4257.1 5415.09,4257.1 5448.27,4223.92 5448.27,4162.92 5519,4092.18 5519,3947.77 5549.27,3917.5 5808.46,3917.5 5853.36,3872.6 v2(5888.27,3872.6)
  Layer 8 w8: v1(2563.27,4847.6) 2564.52,4848.85 2602.02,4848.85 U51.15@2603.27,4847.6
LC_GATE: J13.1 J13.3 Q1.1 Q2.1
  other v1: 6496.27,1149.03 6527.27,1149.03 6535.25,1353.6 6562.63,1353.6
LC_GND: C256.1 C257.2 J13.2 J13.4 Q1.3 Q2.3 | length 131.3
  Layer 1 w50: J13.4@7010,1242 7018.07,1250.07 C256.1@7138,1250.07
  other v1: 6516.3,1233.6 6549.63,1233.6 6516.3,1270.03 6549.63,1270.03
LC_SW_NODE: C257.1 L19.1 Q2.2 | length 128.6
  Layer 1 w50: L19.1@6643,1564 6644.09,1562.91 6644.09,1436.02 C257.1@6644,1435.93
NetC27_1: C27.1 R15.1 U4.4 | length 259.3
  Layer 1 w12: v1(6008.27,2482.6) 6008.27,2483.68 6022.46,2497.87 6022.46,2508.17 R15.1@6028.27,2513.98 ; C27.1@6093.27,2362.6 v1(6113.27,2362.6) 6113.56,2362.6 6131.8,2380.83 U4.4@6141.82,2380.83
  Layer 7 w12: v1(6008.27,2482.6) 6008.27,2467.6 v1(6113.27,2362.6)
NetC28_1: C28.1 R20.1 U4.2 | length 138.8
  Layer 1 w8: C28.1@6093.27,2452.6 6093.27,2483.27 6101.86,2491.86 6101.86,2507.57 R20.1@6108.27,2513.98 ; C28.1@6095,2450 6097.87,2450 6124.58,2423.29 6124.58,2421.28 U4.2@6147.63,2421.28
  Layer 1 w12: C28.1@6090.94,2452.99 C28.1@6094.47,2449.46 C28.1@6095,2449.46
NetC30_1: C30.1 U5.3 | length 71
  Layer 1 w12: U5.3@6081.5,2075.61 U5.3@6088.2,2075.61 6087.29,2074.7 6087.29,2012.71 C30.1@6088,2012
NetC41_2: C41.2 R28.2 R30.2 U8.11 | length 206.7
  Layer 1 w12: C41.2@6361.59,3479.75 6361.59,3507.59 6381.91,3527.91 6381.91,3557.67 U8.11@6383.98,3559.74 ; R28.2@6375.27,3427.6 R28.2@6381.08,3421.79
  Layer 1 w20: R30.2@6360,3389 R30.2@6362.38,3389 6366.31,3389 6370.14,3392.83 6370.14,3425.79 6371.95,3427.6 6375.27,3427.6 R28.2@6375.89,3427.6 6374.27,3429.22 6374.27,3467.07 C41.2@6361.59,3479.75
NetC56_2: C56.2 R33.2 R35.2 U10.11 | length 144.4
  Layer 1 w12: R35.2@7205.32,4425.6 R33.2@7225.65,4425.6 7226.54,4424.7 7226.54,4374.5 7227.44,4373.6 7227.44,4371.63 7208.76,4352.95 7208.76,4312.97 U10.11@7206.69,4310.9
NetC63_2: C63.2 R38.2 R40.2 U12.11 | length 197.6
  Layer 1 w12: U12.11@5949.97,551.05 v1(5989.97,551.05)
  Layer 8 w12: R40.2@5840.57,563.66 R38.2@5874.65,563.66 5876.33,561.98 5926.59,561.98 C63.2@5928.27,560.3 5930.14,558.42 5941.51,558.42 5948.89,551.05 ; 5948.27,552.6 5949.82,551.05 v1(5989.97,551.05) v1@5991.72,551.05
NetC78_2: C78.2 R43.2 R45.2 U14.11 | length 146.1
  Layer 1 w12: v1@5910,262.05 U14.11@5943.82,262.05 ; U14.11@5943.27,262.6 U14.11@5943.82,262.05 ; U14.11@5949.97,262.05 U14.11@5943.82,262.05
  Layer 8 w12: R45.2@5837.34,278.3 5838.47,279.42 5873.52,279.42 R43.2@5874.65,280.55 5874.65,276.61 5880.46,270.8 5884.39,270.8 5893.2,262 5907,262 v1(5908,261) 5909.15,262.15 5915.77,262.15 5926,272.38 C78.2@5926,272.98
NetC85_2: C85.2 R48.2 R50.2 U16.11 | length 202.8
  Layer 1 w10: R48.2@8047,3902 8047,3906.31 8051.94,3911.25 C85.2@8098,3911.25 ; R50.2@8077.62,3859 8081.56,3859 8088.37,3865.81 8088.37,3869.75 8098,3879.38 8098,3908.38 8097.38,3909 C85.2@8097,3909 ; C85.2@8095,3914 8097.22,3914 8119.72,3891.5 U16.11@8169.7,3891.5
NetC100_2: C100.2 R53.2 R55.2 U18.11 | length 190
  Layer 1 w10: R53.2@8054,4336 8058.81,4331.19 8058.81,4312.87 8077.68,4294 R55.2@8081.62,4294 ; R53.2@8054,4342 8054,4341.06 8058.81,4336.25 C100.2@8104,4336.25 ; R55.2@8085.56,4294 R55.2@8092.37,4300.81 ; C100.2@8108.84,4331.16 8124.5,4315.5 U18.11@8169.7,4315.5 U18.11@8166.63,4318.57
NetC107_2: C107.2 R58.2 R60.2 U20.11 | length 195.5
  Layer 1 w10: R58.2@8063,171.38 8063.13,171.25 C107.2@8114.03,171.25 ; R60.2@8084.62,129 8088.56,129 8111.16,151.6 8111.16,168.38 C107.2@8114.03,171.25 ; C107.2@8116,171.25 8118.87,168.38 8131.04,168.38 8139.2,160.22 8187.78,160.22 U20.11@8191,157 ; C107.2@8117,170 8115.75,171.25 C107.2@8114.03,171.25 ; C107.2@8117,172 8114.78,172 C107.2@8114.03,171.25
NetC122_2: C122.2 R63.2 R65.2 U22.11 | length 186.5
  Layer 1 w10: R63.2@8063,613.38 8064.13,612.25 8115.75,612.25 C122.2@8116,612 ; R65.2@8107.62,564 8107.62,605.84 8112.78,611 C122.2@8118,611 ; C122.2@8116,612.25 8117.97,612.25 8136.22,594 U22.11@8187,594
NetC126_1: C126.1 C128.1 R66.2 R67.2 R71.1 U24.3 | length 443.2
  Layer 1 w12: C126.1@5974.24,3306.87 6012.3,3306.87 6024.48,3319.06 6066.06,3319.06 6117.55,3370.55 6163.9,3370.55 6177.35,3384 6198.46,3384 6204.27,3389.81 R71.1@6204.27,3393.32 R66.2@6246.72,3393.32 6246.72,3389.39 6253.89,3382.22 C128.1@6296.27,3382.22 6296.27,3378.28 6302.08,3372.47 6308.56,3372.47 6346.6,3334.43 R67.2@6346.6,3330.5
NetC128_2: C128.2 R69.2 R70.1 | length 98.5
  Layer 1 w12: R70.1@6247.62,3319.06 6251.56,3319.06 6257.37,3324.87 6257.37,3325.89 6266.46,3334.98 C128.2@6296.27,3334.98 6297.13,3334.11 6297.13,3293.87 R69.2@6298,3293
NetC130_1: C130.1 R68.1 R72.2 U24.1 | length 303.8
  Layer 1 w12: R68.1@6011.03,3433.27 6007.18,3437.12 6011.12,3437.12 6016.93,3431.31 6016.93,3427.37 6020.63,3423.67 6020.63,3399.67 6026.44,3393.86 U24.1@6032.36,3393.86 6040.23,3393.86 6054.32,3379.77 6055.63,3379.77 v2@6076.65,3358.75 ; v2@6072.27,3282.86 6072.27,3268.98 ; C130.1@6085.71,3253.6 6072.27,3267.04 6072.27,3268.98 ; R72.2@6087.65,3208.6 6088.65,3209.6 6088.65,3252.6 6072.27,3268.98
  Layer 2 w10: v2(6072,3283) 6076,3287 v2(6076,3359)
NetC130_2: C130.2 R70.2 R72.1 U24.4 | length 180.4
  Layer 1 w12: R72.1@6134.89,3208.6 6135.89,3209.6 6135.89,3252.6 C130.2@6136.89,3253.6 6140.83,3253.6 6146.64,3259.41 6146.64,3281.98 6148.77,3284.11 6148.77,3316.77 U24.4@6150,3318 ; U24.4@6138.76,3317.19 U24.4@6140.63,3319.06 R70.2@6200.38,3319.06
NetC131_1: C131.1 R73.1 R75.2 U25.3 | length 460.8
  Layer 8 w12: R75.2@4919.15,4119.6 4974.43,4119.6 5018.92,4075.1 R73.1@5018.92,3850.09 5019.8,3849.22 C131.1@5076.92,3849.22 5078.53,3847.61 5133.18,3847.61 U25.3@5134.79,3846
NetC138_2: C138.2 R86.2 R87.1 | length 157.5
  Layer 8 w8: R87.1@3824.76,4782.6 3824.76,4696.1 R86.2@3831.27,4689.6 ; R86.2@3833.27,4687.6 R86.2@3831.27,4689.6 ; C138.2@3890.27,4689.6 R86.2@3831.27,4689.6
NetC149_2: C149.2 R99.2 R101.2 U34.11 | length 163.2
  Layer 1 w12: C149.2@5030.57,2000.88 5031.39,2000.88 5033.27,2002.76 5033.27,2015.8 v1(5064.57,2047.1) 5065.33,2047.86 5102.05,2047.86 R99.2@5103.27,2049.08 R101.2@5103.27,2032.72
  Layer 8 w12: U34.11@5018.27,2047.6 5018.77,2047.1 U34.11@5019.57,2047.1 v1(5064.57,2047.1)
NetC164_2: C164.2 R104.2 R106.2 U36.11 | length 152.1
  Layer 1 w12: U36.11@5010,1710 5012.57,1707.43 5051.35,1707.43 5062.03,1696.75 C164.2@5064,1696.75 ; C164.2@5063,1698 5063.62,1698.62 5111.19,1698.62 5117,1704.43 R104.2@5117,1705.62 ; R104.2@5113,1705 5113.81,1705.81 5147.19,1705.81 R106.2@5147.38,1706
NetC171_2: C171.2 R109.2 R111.2 U38.11 | length 157.5
  Layer 8 w12: U38.11@5090.07,3207.6 U38.11@5091.57,3206.1 5137.42,3206.1 5144.45,3213.13 5144.45,3214.85 5146.32,3216.73 C171.2@5148.29,3216.73 5150.17,3214.85 5206.01,3214.85 R109.2@5208.27,3212.6
  Layer 8 w20: R111.2@5208.27,3177.6 5208.9,3178.23 R111.2@5208.9,3179.72 R109.2@5208.9,3208.85
NetC186_2: C186.2 R114.2 R116.2 U40.11 | length 127.6
  Layer 1 w12: U40.11@4995.3,2792.5 4997.37,2790.43 5047.35,2790.43 5054.16,2783.62 5058,2783.62 ; 5058,2784.62 R114.2@5100,2784.62 ; R114.2@5100,2790.62 R116.2@5100,2804.38 5100,2807 R116.2@5102,2809
NetC193_1: C193.1 R120.2 U42.2 | length 130.4
  Layer 1 w12: v1(3152,4122) 3153.33,4123.33 3167.3,4123.33 U42.2@3168.57,4124.6
  Layer 8 w12: C193.1@3090.3,4124.57 v1@3149.3,4124.57 ; v1@3149.97,4123.89 3171.9,4101.97 3171.9,4095.41 3178.71,4088.6 R120.2@3185.27,4088.6
NetC194_1: C194.1 R123.2 U42.1 | length 176.7
  Layer 1 w12: U42.1@3195,4071 U42.1@3196.6,4071 3215.3,4071 3244.85,4100.55 3244.85,4120.85 v1(3246,4122)
  Layer 8 w12: C194.1@3195.65,4173.1 3195.65,4172.12 3208.35,4159.42 3220.89,4159.42 3228.31,4152 R123.2@3230.87,4152 ; C194.1@3196.27,4173.6 C194.1@3202.3,4167.57 ; R123.2@3230.96,4151.91 R123.2@3230.87,4152 ; R123.2@3231,4152 R123.2@3230.87,4152 ; R123.2@3232.27,4153.22 R123.2@3231.65,4152.6 3235.58,4152.6 3241.39,4146.79 3241.39,4128.23 3246.62,4123 v1@3247,4123
NetC195_1: C195.1 U42.6 | length 79.2
  Layer 1 w12: v1(3156,4321) U42.6@3196.6,4321 U42.6@3198.45,4322.85
  Layer 8 w12: C195.1@3141.01,4291.24 3146.82,4297.05 3146.82,4310.97 3156,4320.15 v1(3156,4321)
NetC236_1: C236.1 C238.1 R178.2 R179.2 R183.1 U48.3 | length 245.8
  Layer 8 w12: R183.1@6230,3071 6235.56,3071 R183.1@6238.63,3067.93 ; R183.1@6234.62,3068 6234.69,3067.93 R183.1@6238.63,3067.93 ; C238.1@6246.62,3017 6246.62,3059.94 R183.1@6238.63,3067.93 ; C236.1@6262,3020 6269.13,3012.87 6269.13,2990.25 6275.63,2983.75 6275.63,2979.81 6281.44,2974 R178.2@6285.38,2974 ; U48.3@6282,3069 6280.93,3067.93 R183.1@6238.63,3067.93 ; R178.2@6292,2974 6291.19,2974 6285.38,2968.19 6285.38,2942.24 6302.87,2924.75 6302.87,2920.81 6308.69,2915 R179.2@6312.62,2915
NetC238_2: C238.2 R181.2 R182.1 | length 99
  Layer 8 w12: R182.1@6136,3086.38 6136,3082.44 6160.13,3058.31 6160.13,3040.07 6166.63,3033.57 6166.63,3033.06 6182.69,3017 R181.2@6186.62,3017 R181.2@6193,3017
NetC240_1: C240.1 R180.1 R184.2 U48.1 | length 815.4
  Layer 7 w12: v4(5885.85,3444.44) 5932,3398.29 5932,3260 6031,3161 6206.29,3161 v4(6246.85,3120.44)
  Layer 8 w12: R180.1@5868,3444 5868.44,3444.44 v4(5885.85,3444.44) ; R184.2@6175,3122 6178.62,3118.38 C240.1@6215,3118.38 ; C240.1@6212,3120 6328.99,3120 6348.59,3100.4 6348.59,3073.68 U48.1@6354.4,3067.87
NetC240_2: C240.2 R182.2 R184.1 U48.4 | length 171.4
  Layer 8 w12: R182.2@6136,3133.62 6136,3137.56 6154.31,3155.87 6170.19,3155.87 6178,3163.68 R184.1@6178,3165.62 ; R184.1@6178,3169 R184.1@6178,3165.62 ; C240.2@6213,3167 6273.79,3167 6279.6,3172.81 U48.4@6279.6,3176.13 ; C240.2@6215,3165.62 R184.1@6178,3165.62
NetC242_2: C242.2 R185.2 R187.2 U49.3 | length 183.6
  Layer 8 w20: R187.2@5465.11,3312.29 5465.11,3339.67 5467.09,3341.65 5467.09,3351.39 5468.91,3353.2 5478.42,3353.2 5480.23,3351.39 5480.23,3335.22 5523.11,3335.22 5524.92,3333.41 C242.2@5524.92,3331.98 5524.92,3328.04 5526.73,3326.23 5560.14,3326.23 5578.27,3308.1 R185.2@5578.27,3307.6
NetC243_1: C243.1 R186.2 R187.1 | length 384.7
  Layer 8 w8: R186.2@5257.96,3162.36 5257.96,3138.21 5262.65,3133.53 5423.94,3133.53 5440.91,3150.5 5471.4,3150.5 5484.95,3164.06 5484.95,3216.91 5481.53,3220.34 5469.67,3220.34 5463.3,3226.7 R187.1@5463.3,3267.11
NetC243_2: C243.2 R189.2 R190.1 | length 193.2
  Layer 8 w8: R189.2@5301.18,3161.56 5301.18,3157.8 5308.99,3149.99 5421.31,3149.99 5426,3154.68 5426,3171.44 R190.1@5433.54,3178.98
  Layer 8 w20: R190.1@5433.54,3178.98 5437.48,3178.98 5439.29,3180.8 5461.49,3180.8 5463.3,3182.61 C243.2@5463.3,3183.4
NetC245_1: C245.1 R188.1 R191.2 U49.1 | length 301.2
  Layer 8 w8: C245.1@5414.65,3290.73 5414.65,3410.85 5431.8,3428 U49.1@5476.78,3428 5510.31,3428 5525.71,3412.6 R188.1@5528.27,3412.6
  Layer 8 w20: C245.1@5414.65,3290.73 5415.54,3290.73 5417.35,3288.92 5417.35,3242.26 R191.2@5420.06,3239.55
NetC245_2: C245.2 R190.2 R191.1 U49.4 | length 191.2
  Layer 8 w20: R191.1@5357.07,3239.55 R191.1@5358.05,3239.55 ; U49.4@5368.51,3353.2 5367.96,3352.64 5367.96,3291.29 C245.2@5367.4,3290.73 5367.4,3248.9 R191.1@5358.05,3239.55 ; R190.2@5386.3,3178.98 5386.3,3211.31 R191.1@5358.05,3239.55
NetC247_2: C247.2 R194.2 R196.2 U50.3 | length 327.1
  Layer 8 w20: R194.2@5282.49,3405.94 C247.2@5282.49,3445.41 5333.69,3445.41 5346.66,3458.39 5350.31,3458.39 5369.63,3477.72 5369.63,3483.89 5371.44,3485.7 R196.2@5375.38,3485.7 ; R196.2@5373.27,3482.6 5378.27,3487.6 5450.95,3487.6 5476.45,3513.1 5532.48,3513.1 U50.3@5534.29,3514.91
NetC248_1: C248.1 R195.2 R196.1 | length 113.9
  Layer 8 w20: R195.2@5315.57,3552.31 5316.45,3551.43 5350.88,3551.43 C248.1@5351.76,3550.54 5351.76,3511.56 5344.13,3503.93 5344.13,3497.76 5332.07,3485.7 R196.1@5328.14,3485.7
NetC248_2: C248.2 R199.2 R200.1 | length 91.3
  Layer 8 w12: R199.2@5338.54,3649 5339.86,3650.32 5365.87,3650.32 5365.99,3650.32 R200.1@5368.27,3652.6
  Layer 8 w20: C248.2@5351.76,3597.79 5351.76,3601.73 5353.57,3603.54 5354.16,3603.54 5365.87,3615.25 5365.87,3650.32 R200.1@5365.87,3651.65
NetC250_1: C250.1 R198.1 R202.2 U50.1 | length 195.9
  Layer 8 w20: R202.2@5521.12,3692.47 C250.1@5521.12,3651.65 ; U50.1@5534.73,3590.16 U50.1@5534.29,3589.71 5526.42,3589.71 5521.12,3595.02 C250.1@5521.12,3651.65 ; R198.1@5598.27,3642.6 5598.27,3645.16 5591.78,3651.65 C250.1@5521.12,3651.65
NetC250_2: C250.2 R200.2 R202.1 U50.4 | length 267.2
  Layer 8 w20: R200.2@5413.12,3651.65 C250.2@5473.87,3651.65 ; U50.4@5426.02,3514.91 5438.8,3514.91 5475.77,3551.88 5475.77,3571.35 5473.87,3573.25 C250.2@5473.87,3651.65 ; R202.1@5473.87,3692.47 C250.2@5473.87,3651.65
NetD2_1: D2.1 R119.1 U42.10 | length 3553.5
  Layer 1 w20: v1(2484,1594) 2484,1549 D2.1@2486,1547 ; D2.1@2486.27,1544.34 2512.59,1518.02 2575.59,1518.02 2591.18,1502.43 R119.1@2591.18,1491.6 ; v1(2944,4381) 2952.19,4372.81 2985.38,4372.81 U42.10@2989,4369.19
  Layer 7 w20: v1(2439.27,3507.6) 2338.5,3406.83 2338.5,2631.88 2269.27,2562.65 2269.27,1808.73 v1@2483.85,1594.15 ; v1(2439.27,4162.1) 2495.1,4162.1 2712.5,4379.5 2942.5,4379.5 v1(2944,4381)
  Layer 8 w20: v1(2439.27,3507.6) v1(2439.27,4162.1)
NetD2_2: D2.2 R117.1 | length 107.7
  Layer 1 w20: D2.2@2486.27,1386.86 2584.44,1386.86 R117.1@2591.18,1393.6
NetD3_1: D3.1 R124.1 U42.15 | length 291.4
  Layer 1 w20: v1@2943,4122 2983,4122 U42.15@2984,4121 U42.15@2985,4122
  Layer 8 w20: D3.1@2934,3980 2944,3990 v1(2944,4121) ; D3.1@2936.53,3972.6 2966.26,3942.86 R124.1@2966.26,3881.47
NetD3_2: D3.2 R121.1 | length 113.5
  Layer 8 w20: R121.1@3055.26,3881.47 3066.09,3881.47 3081.68,3897.06 3081.68,3960.27 D3.2@3094.01,3972.6
NetD4_1: D4.1 R127.1 | length 69.2
  Layer 8 w25: D4.1@4443.27,592.6 4445.47,594.8 D4.1@4450.73,594.8 R127.1@4511.54,594.8
NetD5_1: D5.1 R134.1 | length 65.1
  Layer 8 w25: D5.1@4448.69,728.8 R134.1@4509.54,728.8 4512.06,728.8 R134.1@4513.27,727.6
NetD6_1: D6.1 R142.2 | length 57.9
  Layer 8 w25: D6.1@4473.27,262.6 4476.77,259.1 4529.03,259.1 R142.2@4529.53,259.6
NetD7_1: D7.1 R150.2 | length 60.9
  Layer 8 w25: D7.1@4473.15,402.6 4474.15,401.6 4532.27,401.6 R150.2@4533.27,402.6
NetD8_2: D8.2 D9.2 | length 50.8
  Layer 1 w50: D9.2@3476.14,895.57 D8.2@3476.14,946.33
NetJ25_178: J25.178 R84.1 | length 66.9
  Layer 1 w20: v1(5763.27,212.6) 5765.06,214.39 5797.11,214.39 J25.178@5797.27,214.55
  Layer 8 w20: R84.1@5733.27,217.6 5738.27,212.6 v1(5763.27,212.6)
NetJ26_88: J26.88 R93.1 | length 163.5
  Layer 1 w8: v1(5763.27,2427.6) 5764.03,2426.84 5807.51,2426.84 J26.88@5808.27,2427.6 ; J26.88@5823.27,2422.6 J26.88@5828.27,2427.6
  Layer 8 w8: v1(5763.27,2427.6) 5788.78,2453.11 5788.78,2527.09 R93.1@5788.27,2527.6
NetJ26_90: J26.90 R92.1 | length 109.5
  Layer 1 w8: v1(5763.27,2402.6) 5765.43,2402.6 5767.61,2400.43 5800.44,2400.43 J26.90@5808.27,2392.6
  Layer 8 w8: v1(5763.27,2402.6) 5763.27,2400.43 5788.27,2375.43 R92.1@5788.27,2352.6
NetJ26_102: J26.102 R90.1 | length 78.9
  Layer 1 w8: v1(5763.27,2197.6) 5765.43,2197.6 5767.6,2199.76 5795.43,2199.76 J26.102@5803.27,2207.6
  Layer 8 w8: v1(5763.27,2197.6) 5763.27,2216.1 R90.1@5774.76,2227.6
NetJ26_120: J26.120 R89.1 | length 387.6
  Layer 1 w8: v1(5768.27,1902.6) 5769.8,1904.13 5769.8,1908.45 5783.49,1922.14 J26.120@5797.27,1922.14
  Layer 8 w8: R89.1@5749.27,1631.6 5747.27,1629.6 5724.27,1629.6 5687,1666.87 5687,1821.33 v1(5768.27,1902.6)
NetL2_1: L2.1 U7.7 | length 113.9
  Layer 1 w15: U7.7@5398.27,4334.28 5430.28,4334.28 L2.1@5458.93,4362.94
  Layer 1 w20: L2.1@5458.93,4362.94 L2.1@5500.27,4362.94
NetL3_2: L3.2 U9.42 | length 8.3
  Layer 8 w20: U9.42@6261.05,3978.01 U9.42@6266.9,3983.86
  other v1: 6249,4009 6269,4010
NetL4_2: L4.2 U11.42 | length 13.9
  Layer 8 w20: U11.42@6765.9,3987.81 U11.42@6775.7,3978.01
  other v1: 6820.06,3968.14 6820,3988
  other v2: 6978,3881 6998.33,3881 7018.67,3881 7039,3881
NetL5_2: L5.2 U13.42 | length 17.8
  Layer 8 w12: U13.42@7479.49,239.4 U13.42@7492.1,252
  other v1: 7482.5,215.05 7502.27,214.6
NetL6_2: L6.2 U15.42 | length 8.2
  Layer 8 w12: U15.42@6966.32,246.22 U15.42@6972.1,252
  other v1: 6960,216 6981,216
NetL7_2: L7.2 U17.42
  other v1: 9898.02,3029.07 9918.9,3029.07 9669.09,3316.52 9689.97,3316.52
NetL8_2: L8.2 U19.42
  other v1: 10172,3290 10192,3290
  other v2: 10207.87,3026.35 10207.87,3038.9 10207.87,3051.46 10207.87,3064.02 10207.87,3076.58
NetL9_2: L9.2 U21.42
  other v3: 10630,1132 10651,1132
NetL10_2: L10.2 U23.42
  other v2: 10003,1413 10003,1425.67 10003,1438.33 10003,1451
  other v3: 10121,1183 10144,1183
NetL11_1: L11.1 R85.1 U29.7 | length 521.1
  Layer 8 w8: 3228.37,4617.6 3328.27,4617.6 ; 3229.27,4618.1 3218.34,4629.03 3218.34,4672.29 3239.65,4693.6 U29.7@3263.27,4693.6 ; 3329.17,4618.1 3393.67,4682.6 L11.1@3518.27,4682.6 ; L11.1@3516.14,4684.39 3525,4684.39 3538.71,4670.67 3538.71,4645.61 R85.1@3566.73,4617.6
NetL11_2: L11.2 R88.1 U29.6 | length 516.1
  Layer 8 w8: U29.6@3263.27,4742.6 3240.65,4742.6 3218.34,4764.91 3218.34,4808.17 3225.08,4814.91 3418.34,4814.91 3450.44,4782.81 L11.2@3516.14,4782.81 ; L11.2@3513.27,4782.6 3524.78,4782.6 3561.52,4819.34 3561.52,4838.9 3576.22,4853.6 R88.1@3577.21,4853.6
NetL12_2: L12.2 U35.42 | length 284.7
  Layer 1 w25: v1@4446.89,2312.6 4559.61,2312.6 4579.61,2292.6 v1@4723.26,2292.6
  other v1: 4699.58,2292.23 4724.06,2292.23 4444.42,2311.72
NetL13_2: L13.2 U37.42 | length 369.8
  Layer 2 w25: v1@4424,1782 4430,1788 4430,1803 4430,1814.37 4430.11,1814.48 4430.11,1829.11 4465,1864 4519,1864 v1(4632,1751) v1(4654,1751)
  Layer 8 w25: v1@4429.45,1804.45 4436.25,1811.25 4436.25,1825.12 U37.42@4444.42,1833.29
  other v1: 4422,1782 4428,1803
NetL14_2: L14.2 U39.42 | length 319.8
  Layer 1 w50: v1(4478.27,3422.6) v1(4478.27,3402.6) 4478.27,3387.6 4579.87,3286 4711.67,3286 v1(4718.27,3292.6)
  other v1: 4698.27,3292.6
NetL15_2: L15.2 U41.42 | length 8.6
  Layer 8 w20: L15.2@4576.77,2961.16 4582.52,2966.91 L15.2@4582.52,2967.35
NetQ3_1: Q3.1 R12.2 R16.2 R203.1 | length 270.7
  Layer 8 w12: R203.1@5318.27,4212.6 5321.65,4215.98 5321.65,4241.42 5437.08,4241.42 R16.2@5442.9,4235.61 ; R12.2@5402.2,4293.62 5435.95,4293.62 5460.96,4268.61 5460.96,4253.29 5452.64,4244.97 5448.71,4244.97 5442.9,4239.16 R16.2@5442.9,4235.61 ; R16.2@5439.71,4238.41 R16.2@5442.9,4235.22 R16.2@5442.9,4235.61
NetQ3_3: Q3.3 Q4.3 R17.1 | length 131.3
  Layer 8 w12: Q3.3@5547.57,4313.85 5551.51,4313.85 5588.26,4350.6 Q4.3@5633.27,4350.6 ; R17.1@5576.27,4375.98 5576.27,4372.04 5593.27,4355.04 5593.27,4352.6
NetR6_2: R6.2 R8.1 U2.3 | length 99.5
  Layer 1 w12: U2.3@5454.76,3195.21 5454.76,3187.34 5466.45,3175.64 5466.45,3157.1 5472.27,3151.29 R6.2@5476.2,3151.29 5477.39,3152.48 5518.39,3152.48 R8.1@5519.58,3153.67
NetR7_1: R7.1 U2.1 U2.4 | length 192.6
  Layer 1 w12: R7.1@5376.58,3147.91 5378.27,3149.6 5378.27,3193.53 5379.95,3195.21 5379.95,3228.68 5441.07,3289.8 5448.94,3289.8 5454.76,3295.61 U2.4@5454.76,3303.48
NetR9_1: R9.1 R11.2 R14.1 U4.6 | length 411.5
  Layer 1 w12: U4.6@6257.87,2362.23 6258,2362.1 6318.1,2362.1 R9.1@6320,2364 ; R14.1@6268.27,2497.6 6268.27,2505.19 6279.91,2516.83 6287.5,2516.83 v1(6288.27,2517.6) ; R11.2@6318.27,2312.6 6319.65,2313.98 R9.1@6319.65,2362.6
  Layer 7 w12: v1(6288.27,2517.6) 6289.42,2518.75 6289.42,2526.42 6306.1,2543.1 6326.76,2543.1 6342,2527.86 6342,2371.33 v1(6318.27,2347.6)
NetR10_2: R10.2 R13.1 U4.3 | length 199.5
  Layer 1 w8: v1(6048.27,2482.6) 6060.46,2494.79 6060.46,2506.17 R13.1@6068.27,2513.98
  Layer 1 w12: R10.2@6097.25,2402.68 6097.33,2402.6 v1(6118.27,2402.6) 6118.87,2402 6147.23,2402 U4.3@6147.63,2401.6
  Layer 7 w12: v1(6048.27,2482.6) 6049.03,2481.83 6049.03,2471.83 v1(6118.27,2402.6)
NetR16_1: R16.1 U1.6 | length 71.1
  Layer 8 w12: R16.1@5442.9,4187.98 5442.9,4140.98 5445.62,4138.25 U1.6@5445.62,4118
NetR19_1: R19.1 U4.9 | length 73.4
  Layer 1 w8: U4.9@6257.87,2421.28 6258.79,2422.2 6271.2,2422.2 6297.08,2448.08 6313.75,2448.08 R19.1@6318.27,2452.6
NetR21_2: R21.2 R25.1 U7.5 | length 189.5
  Layer 1 w12: U7.5@5402.11,4293.83 5422,4273.94 5422,4124.75 R25.1@5427.59,4119.16 ; R21.2@5414.01,4119.16 R25.1@5417,4122.15
NetR23_1: R23.1 U7.8 | length 125.7
  Layer 1 w12: U7.8@5398.27,4353.97 5398.27,4394.6 5428.2,4424.53 R23.1@5470.91,4424.53
NetR24_1: R24.1 U5.4 | length 52.3
  Layer 1 w12: U5.4@6135.45,2075.61 6142.15,2075.61 6148.26,2069.5 R24.1@6185.26,2069.5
